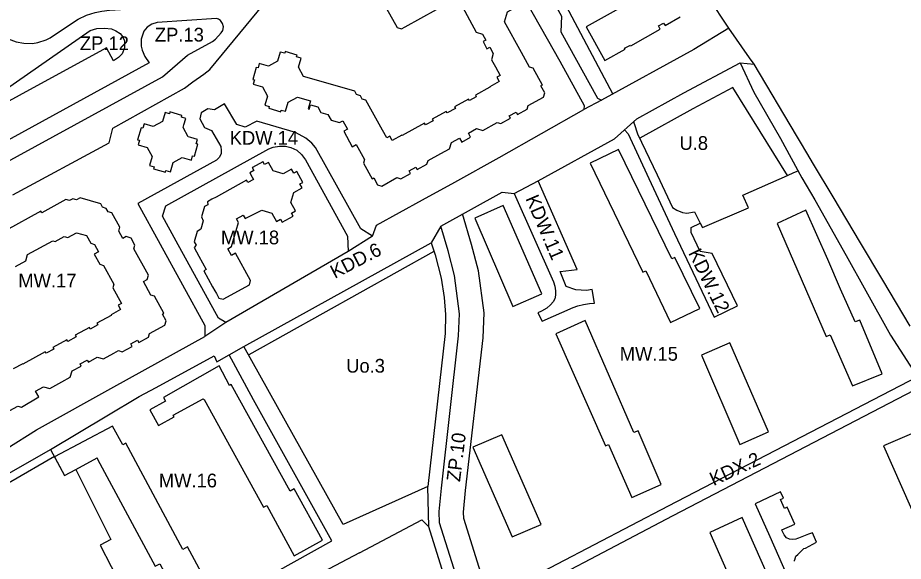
# Model space of a CAD drawing. Extents: x 7426178 to 7427732, y 5548847 to 5550287.
# Drawn here: x 7426935.7 to 7427225.9, y 5549528.9 to 5549707.1 of the extents above; entities that cross this region are included whole.
import ezdxf

# ---------------------------------------------------------------- set-up
doc = ezdxf.new("R2010")
doc.units = 0
for name, color, linetype in [('linie_rozgraniczajace', 7, 'Continuous'), ('linie_zabudowy_nieprzekraczalne', 7, 'Continuous'), ('linie_zabudowy_obowiazujace', 7, 'Continuous'), ('oznaczenia_przeznaczen', 7, 'Continuous')]:
    doc.layers.add(name, color=color, linetype=linetype)

msp = doc.modelspace()

# ---------------------------------------------------------------- linework, layer by layer
at = {"layer": 'linie_rozgraniczajace'}
for p, q in [((7427168.68, 5549703.66), (7427128.13, 5549765.67)), ((7427190.88, 5549668.44), (7427176.96, 5549691.8)), ((7427127, 5549680.04), (7427121.15, 5549677.04)), ((7427137.68, 5549672.38), (7427137.67, 5549673.13)), ((7427192.2, 5549666.24), (7427190.88, 5549668.44)), ((7427194.24, 5549662.81), (7427192.2, 5549666.24)), ((7427098.41, 5549649.49), (7427106.27, 5549653.61)), ((7427074.28, 5549638.8), (7427071.17, 5549633.28)), ((7427051.94, 5549635.43), (7427043.98, 5549630.4)), ((7427228.13, 5549605.99), (7427219.14, 5549621.01)), ((7427003.86, 5549607.18), (7426997, 5549602.57)), ((7427047.66, 5549531.65), (7426995.47, 5549504.35)), ((7427190.3, 5549529.44), (7427190.67, 5549530.56))]:
    msp.add_line(p, q, dxfattribs=at)
for points in [[(7427128.81, 5549764.62), (7427112.63, 5549756.3), (7427109.82, 5549756.54), (7427100.65, 5549752.52), (7427101.35, 5549751.27), (7427098.26, 5549749.58), (7427099.66, 5549747), (7427097.1, 5549745.56), (7427130.69, 5549682.07)], [(7426921.19, 5549708.68), (7426923.92, 5549704.82), (7426932.51, 5549700.17), (7426935.18, 5549699.15), (7426937.7, 5549698.72), (7426940.53, 5549698.67), (7426942.25, 5549698.99), (7426944.97, 5549699.87), (7426946.33, 5549700.48), (7426947.4, 5549701.24), (7426955.49, 5549706.64), (7426958.19, 5549707.88), (7426961.05, 5549708.75), (7426963.27, 5549709.23), (7426965.77, 5549709.6), (7426974.88, 5549710.13), (7426996.27, 5549711.61), (7427000.22, 5549712.16), (7427006.34, 5549713.7), (7427091.63, 5549747.86), (7427113.84, 5549707.59), (7427113.65, 5549702.41), (7427125.67, 5549680.75), (7427127, 5549680.04)], [(7426934.07, 5549648.97), (7426965.67, 5549666.05), (7426966.9, 5549670.9), (7426990.39, 5549683.94), (7426993.06, 5549686.08), (7426996.71, 5549688.56), (7426998.59, 5549690.1), (7427016.19, 5549711.38)], [(7427102.74, 5549711.55), (7427113.31, 5549692.82), (7427121.28, 5549678.28), (7427121.15, 5549677.04)], [(7427168.68, 5549703.66), (7427157.27, 5549696.66), (7427127, 5549680.04)], [(7427176.96, 5549691.8), (7427175.46, 5549693.95), (7427168.68, 5549703.66)], [(7427138.58, 5549673.94), (7427154, 5549682.48), (7427172.45, 5549692.34), (7427176.96, 5549691.8)], [(7427172.45, 5549692.34), (7427176.9, 5549682.64), (7427185.66, 5549667.5), (7427192.62, 5549654.65), (7427196.91, 5549647.34), (7427207.1, 5549629.09), (7427213.58, 5549617.58), (7427221.64, 5549603.03), (7427231.15, 5549588.29), (7427237.07, 5549577.28), (7427238.15, 5549575.04), (7427242.34, 5549566.53), (7427249.94, 5549551.24), (7427251.6, 5549547.85), (7427259.67, 5549530.97), (7427260.96, 5549529.16), (7427268.09, 5549512.22), (7427275.65, 5549494.4), (7427277.61, 5549486.99), (7427289.94, 5549458.65)], [(7427051.94, 5549635.43), (7427048.12, 5549637.92), (7427033.26, 5549664.53), (7427032.06, 5549665.91), (7427030.15, 5549667.58), (7427026.68, 5549669.49), (7427013.99, 5549673.17), (7427010.19, 5549671.21), (7427007.48, 5549672.06), (7427003.49, 5549678.86), (7427000.12, 5549676.93), (7426998.02, 5549677.21), (7426995.8, 5549675.94), (7426995.35, 5549673.94), (7426996.88, 5549671.05), (7426999.23, 5549670.11), (7427002.29, 5549664.84), (7427002.4, 5549663.5), (7427002.33, 5549662.62), (7427001.76, 5549661.32), (7427000.86, 5549660.43), (7426975.01, 5549646.13), (7426997.05, 5549606.25), (7426997, 5549602.57)], [(7427051.94, 5549635.43), (7427053.3, 5549639.06), (7427068.31, 5549647.41), (7427078.91, 5549653.22), (7427093.4, 5549661.27), (7427121.15, 5549677.04)], [(7427106.27, 5549653.61), (7427131.24, 5549667.41), (7427138.58, 5549673.94)], [(7427137.68, 5549672.38), (7427138.81, 5549669.06), (7427145.2, 5549655.59), (7427150.27, 5549644.88), (7427151.7, 5549644.01), (7427153.51, 5549643.28), (7427154.91, 5549643.06), (7427157.4, 5549643.45), (7427159.35, 5549639.77)], [(7427134.53, 5549670.34), (7427135.67, 5549669.07), (7427142.53, 5549654.4), (7427150.92, 5549636.39), (7427163.9, 5549608.89), (7427171.54, 5549612.64), (7427163.22, 5549629.85), (7427159.28, 5549630.46), (7427156.4, 5549636.68), (7427156.4, 5549638.35), (7427159.35, 5549639.77)], [(7427043.98, 5549630.4), (7427003.86, 5549607.18), (7427001.48, 5549608.55), (7426987.58, 5549633.8), (7426983.08, 5549642), (7426984.18, 5549645.42), (7427017.95, 5549664.09), (7427019.4, 5549664.65), (7427021.44, 5549665), (7427023.42, 5549664.98), (7427025.17, 5549664.53), (7427027.13, 5549663.64), (7427028.72, 5549662.19), (7427029.95, 5549660.54), (7427043.78, 5549635.45), (7427043.98, 5549630.4)], [(7427202.88, 5549648.34), (7427196.45, 5549659.1), (7427194.24, 5549662.81)], [(7427159.35, 5549639.77), (7427160.12, 5549638.32), (7427175.14, 5549644.76), (7427173.29, 5549648.96), (7427187.89, 5549655.35), (7427190.05, 5549656.3), (7427191.38, 5549656.94)], [(7427074.28, 5549638.8), (7427094.42, 5549649.94), (7427098.41, 5549649.49), (7427111.3, 5549620.52), (7427111.68, 5549619.11), (7427111.94, 5549617.57), (7427111.9, 5549616.13), (7427111.64, 5549614.95), (7427111.13, 5549613.92), (7427110.32, 5549613.01), (7427109.08, 5549611.91), (7427107.31, 5549610.85), (7427106.13, 5549610.3), (7427107.5, 5549607.63), (7427117.64, 5549612.15), (7427119.27, 5549612.63), (7427121.12, 5549613.06), (7427123.05, 5549613.44), (7427124.71, 5549613.47), (7427124.71, 5549613.47), (7427123.94, 5549617.95), (7427122.09, 5549617.63), (7427118.57, 5549617.86), (7427115.44, 5549618.98), (7427113.45, 5549623.95), (7427119.05, 5549624.51), (7427106.27, 5549653.61)], [(7427219.14, 5549621.01), (7427211.82, 5549633.34), (7427202.88, 5549648.34)], [(7427090.22, 5549516.36), (7427081.87, 5549542.92), (7427081.79, 5549544.97), (7427082.46, 5549552.09), (7427088.15, 5549602.17), (7427088.49, 5549610.35), (7427086.67, 5549624.17), (7427084.42, 5549632.79), (7427081.45, 5549642.76)], [(7427230.48, 5549589.38), (7427148.85, 5549546.95), (7427088.25, 5549515.33), (7427086.86, 5549515.01), (7427085.02, 5549515.09), (7427083.04, 5549515.77), (7427081.79, 5549516.82), (7427081.29, 5549518.09), (7427073.92, 5549541.54), (7427073.78, 5549545.19), (7427074.5, 5549552.91), (7427080.17, 5549602.79), (7427080.47, 5549609.99), (7427078.8, 5549622.63), (7427076.71, 5549630.64), (7427074.28, 5549638.8)], [(7427004.97, 5549596.59), (7427009.83, 5549599.36), (7427071.17, 5549633.28)], [(7427071.17, 5549633.28), (7427072.46, 5549629.38), (7427074.43, 5549621.69), (7427075.38, 5549615.43), (7427075.85, 5549609.83), (7427075.76, 5549603.56), (7427070.06, 5549553.47)], [(7426932.15, 5549565.9), (7426941.86, 5549571.96), (7426967.18, 5549586.1), (7426997, 5549602.57)], [(7427070.06, 5549553.47), (7427042.32, 5549540.95), (7427009.83, 5549599.36)], [(7426946.41, 5549565.6), (7426964.89, 5549576.61), (7426975.52, 5549582.98), (7426981.02, 5549585.85), (7427000.05, 5549596.21), (7427000.96, 5549594.3), (7427004.97, 5549596.59)], [(7426981.55, 5549508.5), (7426983.59, 5549504.94), (7427038.6, 5549535.58), (7427012.99, 5549581.89), (7427004.97, 5549596.59)], [(7427115.22, 5549413.02), (7427108.83, 5549432.27), (7427108.83, 5549432.27), (7427092.63, 5549482.16), (7427086.13, 5549502.57), (7427086.04, 5549505.04), (7427086.55, 5549507.51), (7427087.93, 5549510.29), (7427089.87, 5549512.02), (7427150.51, 5549543.92), (7427232.16, 5549586.41)], [(7426911.56, 5549537.38), (7426911.05, 5549539.62), (7426911.32, 5549542.39), (7426912.47, 5549544.85), (7426914.67, 5549546.95), (7426922.71, 5549552.03), (7426932.12, 5549557.37), (7426946.41, 5549565.6)], [(7426946.41, 5549565.6), (7426951.05, 5549557.05), (7426954.75, 5549559.04), (7426966.21, 5549536.1), (7426962.71, 5549534.23), (7426977.08, 5549506.2)], [(7427123.34, 5549380.95), (7427116.69, 5549397.29), (7427113.13, 5549407.11), (7427105.56, 5549430.76), (7427089.3, 5549481.03), (7427079.5, 5549511.18), (7427070.38, 5549540.22), (7427070.06, 5549553.47)], [(7427190.67, 5549530.56), (7427191.28, 5549531.14), (7427193.29, 5549533.06), (7427193.78, 5549533.26), (7427197.44, 5549535.16), (7427196.08, 5549538.24), (7427194.85, 5549537.76), (7427191.55, 5549536.47), (7427191.18, 5549536.36), (7427190.65, 5549536.19), (7427189.41, 5549536.04), (7427188.63, 5549536.12), (7427187.62, 5549536.62), (7427186.79, 5549537.54), (7427186.17, 5549538.89), (7427186.06, 5549539.19), (7427190.29, 5549541.08), (7427187.8, 5549546.61), (7427186.92, 5549546.26), (7427185.64, 5549549.16), (7427186.64, 5549549.6), (7427185.63, 5549551.64), (7427177.3, 5549547.79), (7427182.1, 5549537.03), (7427184.96, 5549530.59), (7427189.29, 5549520.68)], [(7427047.66, 5549531.65), (7427068.12, 5549542.52), (7427070.38, 5549540.22)], [(7427190.67, 5549530.56), (7427190.67, 5549530.56)]]:
    msp.add_lwpolyline(points, dxfattribs=at)
for points in [[(7426915.26, 5549657.59), (7426918.14, 5549652.2), (7426983.18, 5549687.7), (7426991.34, 5549694.79), (7426999.55, 5549699.32), (7427000.52, 5549700.08), (7427002.33, 5549702.14), (7427002.85, 5549702.91), (7427003.13, 5549704.1), (7427002.83, 5549705.21), (7427002.12, 5549706.15), (7427001.44, 5549706.64), (7427000.79, 5549706.81), (7426981.34, 5549705.51), (7426979.64, 5549704.94), (7426978.1, 5549704.02), (7426977, 5549702.63), (7426976.19, 5549699.99), (7426976.18, 5549697.79), (7426976.42, 5549696.42), (7426977.37, 5549694.34), (7426978.74, 5549692.27)], [(7426909.9, 5549661.64), (7426908.7, 5549661.09), (7426907.17, 5549660.78), (7426905.84, 5549660.95), (7426904.88, 5549661.62), (7426904.36, 5549662.8), (7426904.38, 5549663.77), (7426905.1, 5549665.03), (7426918.22, 5549674.28), (7426959.43, 5549702.93), (7426961.6, 5549703.49), (7426964.15, 5549703.68), (7426966.39, 5549703.42), (7426967.87, 5549702.82), (7426969.25, 5549701.93), (7426970.04, 5549700.89), (7426970.63, 5549699.48), (7426970.63, 5549697.16), (7426969.89, 5549695.21), (7426968.73, 5549693.98), (7426967.09, 5549692.91), (7426964.77, 5549697.22), (7426907.49, 5549665.94)]]:
    msp.add_lwpolyline(points, close=True, dxfattribs=at)
for centre, start, end in [((7427190.48, 5549529.12), 119.6907, 211.3515), ((7427191.04, 5549530.53), 174.7917, 175.0834)]:
    msp.add_arc(centre, 0.375, start, end, dxfattribs=at)
at = {"layer": 'linie_zabudowy_nieprzekraczalne'}
msp.add_line((7427187.89, 5549655.35), (7427170, 5549684.23), dxfattribs=at)
for points in [[(7427170, 5549684.23), (7427156.87, 5549677.21), (7427139.51, 5549667.6)], [(7427072.09, 5549630.5), (7427011.39, 5549596.55)], [(7426947.78, 5549563.22), (7426933.48, 5549554.99), (7426924.12, 5549549.68), (7426916.37, 5549544.78), (7426914.74, 5549543.22), (7426914, 5549541.66), (7426913.82, 5549539.8), (7426914.67, 5549536.07), (7426905.95, 5549530.97)]]:
    msp.add_lwpolyline(points, dxfattribs=at)
at = {"layer": 'linie_zabudowy_obowiazujace'}
for p, q in [((7427080.73, 5549711.8), (7427085.96, 5549702.29)), ((7427090.92, 5549693.28), (7427092.19, 5549690.97)), ((7427092.19, 5549690.97), (7427093.74, 5549688.14)), ((7427034.39, 5549686.38), (7427029.3, 5549687.86)), ((7427046.13, 5549682.98), (7427034.39, 5549686.38)), ((7427093.74, 5549688.14), (7427092.7, 5549687.57)), ((7427046.74, 5549681.86), (7427046.13, 5549682.98)), ((7427047.96, 5549681.51), (7427046.74, 5549681.86)), ((7427048.58, 5549680.39), (7427047.96, 5549681.51)), ((7427049.81, 5549680.04), (7427048.58, 5549680.39)), ((7427055.19, 5549670.24), (7427049.81, 5549680.04)), ((7427085.67, 5549681.66), (7427085.96, 5549681.13)), ((7427079.13, 5549677.37), (7427076.38, 5549675.86)), ((7427078.84, 5549677.9), (7427079.13, 5549677.37)), ((7427076.09, 5549676.39), (7427071.48, 5549673.85)), ((7427076.38, 5549675.86), (7427076.09, 5549676.39)), ((7427046.64, 5549665.52), (7427049.33, 5549660.65)), ((7426955, 5549636.59), (7426958.27, 5549635.65)), ((7426948, 5549633.76), (7426950.89, 5549635.35)), ((7426960.87, 5549632.79), (7426962.21, 5549630.39)), ((7426938.36, 5549627.42), (7426938.95, 5549629.46)), ((7426935, 5549625.57), (7426938.36, 5549627.42)), ((7426966.84, 5549618.54), (7426969.67, 5549613.41)), ((7426969.42, 5549611.39), (7426966.27, 5549609.65)), ((7426966.34, 5549609.52), (7426961.63, 5549606.93)), ((7426966.27, 5549609.65), (7426966.34, 5549609.52)), ((7426961.92, 5549606.4), (7426959.46, 5549605.04)), ((7426961.63, 5549606.93), (7426961.92, 5549606.4)), ((7426951.81, 5549601.52), (7426947.18, 5549598.98)), ((7426952.1, 5549600.99), (7426951.81, 5549601.52)), ((7426954.83, 5549602.5), (7426952.1, 5549600.99)), ((7426945.01, 5549597.1), (7426944.72, 5549597.62)), ((7426970.1, 5549567.12), (7426966.75, 5549573.23)), ((7426951.05, 5549557.05), (7426954.75, 5549559.04))]:
    msp.add_line(p, q, dxfattribs=at)
for points in [[(7427100.74, 5549695.68), (7427095.24, 5549705.69), (7427096.19, 5549708.97), (7427098.93, 5549710.48), (7427095.52, 5549716.66), (7427092.78, 5549715.15), (7427089.49, 5549716.11), (7427087.3, 5549720.1), (7427086.08, 5549720.45), (7427083.71, 5549724.74), (7427084.07, 5549725.96), (7427082.96, 5549727.98), (7427081.56, 5549728.39), (7427079.41, 5549727.21), (7427070.08, 5549722.07), (7427069.73, 5549720.84), (7427055.97, 5549713.28), (7427055.57, 5549711.88), (7427060.01, 5549703.82), (7427061.41, 5549703.42), (7427062.67, 5549704.11), (7427078.05, 5549712.58)], [(7427138.71, 5549713.53), (7427121.95, 5549704.07), (7427128.08, 5549693.09), (7427134.71, 5549696.78), (7427134.56, 5549697.04), (7427136.47, 5549698.1), (7427136.61, 5549697.84), (7427146.24, 5549703.31), (7427145.65, 5549704.37), (7427147.34, 5549705.32), (7427147.81, 5549704.55), (7427152.74, 5549707.32)], [(7427085.96, 5549702.29), (7427087.99, 5549701.71), (7427089.07, 5549699.76), (7427088.15, 5549699.26), (7427089.45, 5549696.88), (7427090.37, 5549697.39), (7427091.52, 5549695.31), (7427090.92, 5549693.28)], [(7427029.3, 5549687.86), (7427027.65, 5549690.84), (7427028.53, 5549693.86), (7427027.09, 5549694.28), (7427027.25, 5549694.85), (7427023.33, 5549695.99), (7427023.17, 5549695.41), (7427021.73, 5549695.83), (7427020.85, 5549692.82), (7427017.87, 5549691.17), (7427014.85, 5549692.05), (7427014.43, 5549690.6), (7427013.86, 5549690.77), (7427012.72, 5549686.86), (7427013.3, 5549686.69), (7427012.88, 5549685.25), (7427015.9, 5549684.38), (7427017.54, 5549681.39), (7427016.66, 5549678.38), (7427018.1, 5549677.96), (7427017.94, 5549677.38), (7427021.85, 5549676.24), (7427022.02, 5549676.82), (7427023.46, 5549676.4), (7427024.34, 5549679.42), (7427027.32, 5549681.06), (7427031.61, 5549679.82)], [(7427074.37, 5549662.58), (7427077.2, 5549664.14), (7427077.79, 5549666.18), (7427080.46, 5549667.65), (7427081.19, 5549666.33), (7427084.08, 5549667.93), (7427083.35, 5549669.24), (7427086.02, 5549670.71), (7427088.07, 5549670.12), (7427092.8, 5549672.72), (7427094.01, 5549672.37), (7427097.2, 5549674.13), (7427096.77, 5549674.91), (7427098.97, 5549676.13), (7427099.41, 5549675.34), (7427102.6, 5549677.1), (7427102.96, 5549678.32), (7427107.95, 5549681.07), (7427108.36, 5549682.46), (7427107.12, 5549684.72), (7427107.64, 5549685), (7427104.59, 5549690.55), (7427103.37, 5549690.9), (7427100.74, 5549695.68)], [(7427092.7, 5549687.57), (7427093.49, 5549686.13), (7427090.34, 5549684.4), (7427090.41, 5549684.26), (7427085.67, 5549681.66)], [(7427031.61, 5549679.82), (7427030.86, 5549677.22), (7427031.23, 5549677.12), (7427031.65, 5549678.56), (7427034, 5549677.87), (7427035.03, 5549676.02), (7427037.33, 5549675.34), (7427038.35, 5549673.49), (7427041.14, 5549672.68), (7427042.25, 5549673.29), (7427043.76, 5549670.55), (7427042.53, 5549669.87), (7427045.32, 5549664.81), (7427046.64, 5549665.52)], [(7427085.96, 5549681.13), (7427083.73, 5549679.91), (7427083.45, 5549680.43), (7427078.84, 5549677.9)], [(7426978.91, 5549658.59), (7426980.35, 5549658.17), (7426980.18, 5549657.59), (7426984.1, 5549656.46), (7426984.27, 5549657.03), (7426985.71, 5549656.61), (7426986.58, 5549659.63), (7426989.57, 5549661.27), (7426992.58, 5549660.4), (7426993, 5549661.84), (7426993.58, 5549661.67), (7426994.71, 5549665.59), (7426994.14, 5549665.75), (7426994.56, 5549667.19), (7426992.44, 5549667.81), (7426991.54, 5549668.07), (7426989.9, 5549671.06), (7426990.16, 5549671.96), (7426990.77, 5549674.07), (7426989.33, 5549674.49), (7426989.5, 5549675.06), (7426985.58, 5549676.2), (7426985.42, 5549675.62), (7426983.98, 5549676.04), (7426983.1, 5549673.03), (7426980.11, 5549671.39), (7426977.1, 5549672.26), (7426976.68, 5549670.82), (7426976.11, 5549670.99), (7426974.97, 5549667.07), (7426975.54, 5549666.9), (7426975.13, 5549665.46), (7426978.14, 5549664.59), (7426979.78, 5549661.6), (7426978.91, 5549658.59)], [(7427069.3, 5549671.96), (7427069.02, 5549672.5), (7427061.66, 5549668.44), (7427061.58, 5549668.57), (7427058.43, 5549666.83)], [(7427071.48, 5549673.85), (7427071.77, 5549673.32), (7427069.3, 5549671.96)], [(7427058.43, 5549666.83), (7427057.63, 5549668.28), (7427056.59, 5549667.71), (7427055.19, 5549670.24)], [(7427049.33, 5549660.65), (7427048.98, 5549659.42), (7427051.81, 5549654.27), (7427052.34, 5549654.56), (7427053.57, 5549652.32), (7427054.97, 5549651.91), (7427059.96, 5549654.66), (7427061.19, 5549654.3), (7427064.37, 5549656.05), (7427063.94, 5549656.84), (7427066.16, 5549658.07), (7427066.59, 5549657.28), (7427069.77, 5549659.03), (7427070.13, 5549660.25), (7427074.37, 5549662.58)], [(7427123.28, 5549659.44), (7427140.56, 5549623.64), (7427141.45, 5549624.07), (7427149.62, 5549607.16), (7427159.23, 5549611.72), (7427151.06, 5549628.53), (7427150.01, 5549628.02), (7427132.59, 5549663.86), (7427123.28, 5549659.44)], [(7427027.16, 5549656.7), (7427026.17, 5549656.16), (7427025.45, 5549657.47), (7427022.7, 5549655.96), (7427019.43, 5549656.91), (7427017.91, 5549659.66), (7427016.6, 5549658.94), (7427016.06, 5549659.92), (7427015.98, 5549659.88), (7427012.57, 5549657.99), (7427012.49, 5549657.95), (7427013.03, 5549656.97), (7427011.71, 5549656.25), (7427012.51, 5549654.8), (7427012.94, 5549654.01), (7427011.13, 5549653.02), (7427010.69, 5549653.8), (7427000.69, 5549648.31), (7426999.31, 5549647.56), (7426997.89, 5549646.77), (7426997.97, 5549645.77), (7426996.86, 5549645.17), (7426995.89, 5549641.8), (7426996.44, 5549640.48), (7426995.66, 5549637.8), (7426994.49, 5549636.99), (7426993.51, 5549633.62), (7426994.12, 5549632.51), (7426993.51, 5549631.77), (7426994.3, 5549630.33), (7426995.04, 5549628.97), (7426997.45, 5549624.6), (7426996.66, 5549624.17), (7426999.55, 5549618.92), (7427000.3, 5549617.55), (7427000.78, 5549616.68), (7427001.6, 5549615.2), (7427003.01, 5549614.79), (7427011.59, 5549619.51), (7427012, 5549620.92), (7427007.07, 5549629.9), (7427005.75, 5549629.17), (7427004.54, 5549631.38), (7427005.73, 5549632.04), (7427008.03, 5549639.97), (7427007.38, 5549641.16), (7427009.58, 5549642.37), (7427010.21, 5549641.23), (7427015.69, 5549644.02), (7427018.96, 5549643.07), (7427020.47, 5549640.32), (7427021.79, 5549641.04), (7427022.33, 5549640.06), (7427025.9, 5549642.03), (7427025.36, 5549643.01), (7427026.67, 5549643.73), (7427025.15, 5549646.48), (7427026.11, 5549649.76), (7427028.86, 5549651.27), (7427028.14, 5549652.58), (7427029.12, 5549653.12), (7427027.16, 5549656.7)], [(7426970.12, 5549634.75), (7426968.8, 5549637.16), (7426969.15, 5549638.38), (7426966.55, 5549643.12), (7426965.32, 5549643.47), (7426964.72, 5549644.58), (7426963.49, 5549644.93), (7426962.88, 5549646.05), (7426956.11, 5549648.01), (7426954.99, 5549647.4), (7426953.77, 5549647.75), (7426952.66, 5549647.14), (7426951.43, 5549647.49), (7426943.56, 5549643.16), (7426943.27, 5549643.68), (7426931.81, 5549637.38), (7426932.1, 5549636.85), (7426929.56, 5549635.46)], [(7427085.42, 5549641.36), (7427097.93, 5549612.39), (7427107.44, 5549616.57), (7427094.74, 5549645.5), (7427085.42, 5549641.36)], [(7427184.54, 5549639.68), (7427200.63, 5549602.64), (7427201.9, 5549603.16), (7427209.21, 5549586.41), (7427218.93, 5549590.38), (7427211.62, 5549607.98), (7427210.12, 5549607.38), (7427205.26, 5549618.06), (7427201.09, 5549627.79), (7427193.88, 5549644), (7427184.54, 5549639.68)], [(7426950.89, 5549635.35), (7426952.12, 5549635), (7426955, 5549636.59)], [(7426938.95, 5549629.46), (7426947.18, 5549634), (7426948, 5549633.76)], [(7426958.27, 5549635.65), (7426959.64, 5549633.16), (7426960.87, 5549632.79)], [(7426967.14, 5549597.08), (7426968.75, 5549597.97), (7426969.96, 5549597.61), (7426973.15, 5549599.37), (7426972.72, 5549600.16), (7426974.92, 5549601.38), (7426975.36, 5549600.59), (7426978.55, 5549602.34), (7426978.91, 5549603.56), (7426983.9, 5549606.31), (7426984.31, 5549607.72), (7426983.08, 5549609.96), (7426983.6, 5549610.25), (7426980.55, 5549615.81), (7426979.32, 5549616.16), (7426976.88, 5549620.59), (7426978.07, 5549621.25), (7426978.49, 5549622.67), (7426973.71, 5549631.34), (7426974.06, 5549632.55), (7426972.81, 5549634.83), (7426971.23, 5549635.36), (7426970.12, 5549634.75)], [(7426962.21, 5549630.39), (7426960.77, 5549629.6), (7426962.61, 5549626.25), (7426963.83, 5549625.9)], [(7426963.83, 5549625.9), (7426967.2, 5549619.77), (7426966.84, 5549618.54)], [(7426969.67, 5549613.41), (7426968.62, 5549612.83), (7426969.42, 5549611.39)], [(7426922.72, 5549608.12), (7426919.87, 5549606.55), (7426911.76, 5549602.09), (7426911.36, 5549600.67), (7426912.61, 5549598.4), (7426913.84, 5549598.05), (7426916.17, 5549593.8), (7426918.1, 5549594.86), (7426921.03, 5549589.52), (7426922.52, 5549590.34), (7426925.03, 5549585.77), (7426924.69, 5549584.55), (7426927.52, 5549579.39), (7426928.04, 5549579.68), (7426929.27, 5549577.44), (7426930.69, 5549577.03), (7426935.68, 5549579.78), (7426936.89, 5549579.44), (7426942.59, 5549582.82), (7426941.49, 5549584.68), (7426944.16, 5549586.15), (7426946.2, 5549585.56), (7426950.15, 5549587.74)], [(7427128.34, 5549566.79), (7427129.24, 5549567.19), (7427136.95, 5549549.88), (7427146.5, 5549554.13), (7427138.95, 5549571.73), (7427137.52, 5549571.11), (7427121.58, 5549607.8), (7427111.99, 5549603.52), (7427128.34, 5549566.79)], [(7426959.46, 5549605.04), (7426959.17, 5549605.57), (7426954.54, 5549603.02), (7426954.83, 5549602.5)], [(7426947.18, 5549598.98), (7426947.47, 5549598.45), (7426945.01, 5549597.1)], [(7427172.33, 5549567.25), (7427181.7, 5549571.3), (7427169.08, 5549600.48), (7427159.72, 5549596.43), (7427172.33, 5549567.25)], [(7426944.72, 5549597.62), (7426937.39, 5549593.56), (7426937.32, 5549593.69), (7426934.17, 5549591.95)], [(7426950.15, 5549587.74), (7426952.92, 5549589.26), (7426953.51, 5549591.3), (7426956.5, 5549592.9), (7426956.13, 5549593.59), (7426958.49, 5549594.89), (7426958.89, 5549594.22), (7426961.74, 5549595.83), (7426963.78, 5549595.24), (7426967.14, 5549597.08)], [(7427005.12, 5549586.57), (7427001.69, 5549592.95), (7426983.45, 5549582.6), (7426984.09, 5549581.44)], [(7426996.73, 5549581.91), (7427016.26, 5549546.67), (7427017.28, 5549547.22), (7427026.23, 5549530.69), (7427035.58, 5549535.87), (7427026.29, 5549552.63), (7427024.97, 5549551.9), (7427005.62, 5549586.83), (7427005.12, 5549586.57)], [(7426984.09, 5549581.44), (7426978.97, 5549578.6), (7426981.82, 5549573.48), (7426986.94, 5549576.32), (7426986.67, 5549576.8)], [(7426986.67, 5549576.8), (7426996.47, 5549582.2), (7426996.73, 5549581.91)], [(7426966.75, 5549573.23), (7426947.72, 5549563.19), (7426951.05, 5549557.05)], [(7427097.68, 5549536.89), (7427107.16, 5549541.02), (7427094.35, 5549570.42), (7427084.87, 5549566.29), (7427097.68, 5549536.89)], [(7427219.41, 5549566.73), (7427254.28, 5549487.73), (7427265.14, 5549492.55), (7427230.12, 5549571.35), (7427219.41, 5549566.73)], [(7426961.83, 5549562.39), (7426980.72, 5549527.28), (7426982.23, 5549528.09), (7426991.25, 5549511.32), (7427000.49, 5549516.61), (7426991.33, 5549533.62), (7426989.83, 5549532.81), (7426971.07, 5549567.67), (7426970.1, 5549567.12)], [(7426954.75, 5549559.04), (7426961.7, 5549562.86), (7426961.83, 5549562.39)], [(7427162.46, 5549538.41), (7427197.02, 5549459.84), (7427207.9, 5549464.38), (7427173.12, 5549543.27), (7427162.46, 5549538.41)]]:
    msp.add_lwpolyline(points, dxfattribs=at)

# ---------------------------------------------------------------- texts
at = {"layer": 'oznaczenia_przeznaczen'}
for s, p in [('ZP.13', (7426980.64, 5549699.27)), ('ZP.12', (7426956.07, 5549696.46)), ('KDW.14', (7427005.15, 5549665.45)), ('U.8', (7427152.52, 5549663.75)), ('MW.18', (7427002.28, 5549632.8)), ('MW.17', (7426935.88, 5549618.67)), ('MW.15', (7427132.96, 5549594.66)), ('Uo.3', (7427043.31, 5549590.75)), ('MW.16', (7426981.93, 5549553.15))]:
    msp.add_text(s, height=4.5, dxfattribs=at).set_placement(p)
for s, rotation, p in [('KDW.11', 293.1958, (7427101.97, 5549647.82)), ('KDD.6', 27.3419, (7427039.59, 5549621.43)), ('KDW.12', 296.0487, (7427155.32, 5549629.99)), ('ZP.10', 83.0519, (7427080.62, 5549554.83)), ('KDX.2', 24.6698, (7427163.69, 5549553.56))]:
    msp.add_text(s, height=4.5, rotation=rotation, dxfattribs=at).set_placement(p)

doc.saveas('drawing.dxf')
